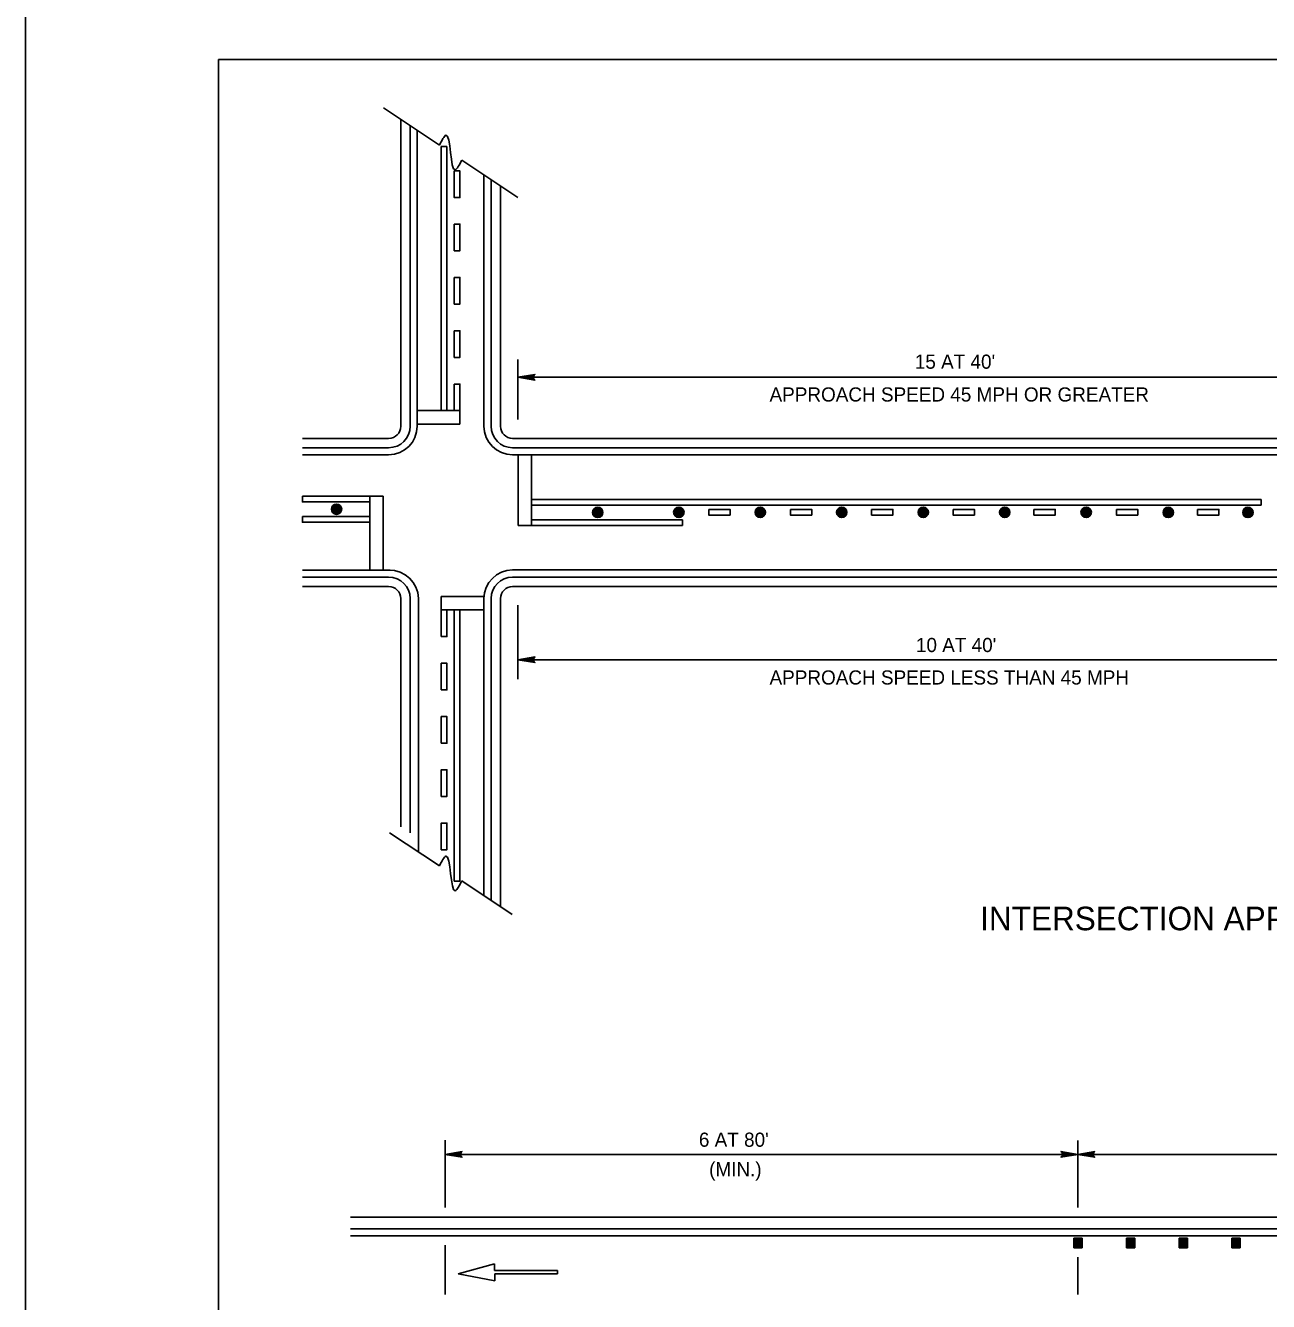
# Model space of a CAD drawing. Extents: x 639362 to 641108, y 298458 to 299646.
# Drawn here: x 639362.3 to 639626, y 298773.7 to 299044.4 of the extents above; entities that cross this region are included whole.
import ezdxf

# ---------------------------------------------------------------- set-up
doc = ezdxf.new("R2010")
doc.units = 0
for name, color, linetype in [('1', 7, 'Continuous'), ('2', 7, 'Continuous'), ('3', 7, 'Continuous'), ('PLT-BNDY', 7, 'Continuous')]:
    doc.layers.add(name, color=color, linetype=linetype)

# ---------------------------------------------------------------- blocks, each defined once
blk = doc.blocks.new('RARROW')
at = {"layer": '3'}
blk.add_lwpolyline([(-2.2695, 0.285), (-2.184875, 0.12075), (0, 0), (-2.2695, 0.285), (-2.38575, 0.384625), (0, 0), (-2.183125, -0.108), (-2.262875, -0.2705), (0, 0), (-2.38575, -0.379125), (-2.262875, -0.2705)], dxfattribs=at)

msp = doc.modelspace()

# ---------------------------------------------------------------- linework, layer by layer
at = {"layer": '1'}
for q in [(640189.27, 299037.19), (639403.27, 298473.19)]:
    msp.add_line((639403.27, 299037.19), q, dxfattribs=at)
at = {"layer": '2'}
for p, q in [((639450.1, 299019.03), (639438.22, 299026.95)), ((639441.9, 298959.38), (639441.9, 299024.5)), ((639443.9, 298959.38), (639443.9, 299023.16)), ((639445.4, 298959.38), (639445.4, 299022.16)), ((639450.51, 298962.69), (639450.51, 299018.73)), ((639450.51, 299018.73), (639451.71, 299018.73)), ((639451.71, 299018.73), (639451.71, 298962.69)), ((639466.76, 299007.92), (639454.86, 299015.86)), ((639459.55, 298959.38), (639459.55, 299012.73)), ((639461.05, 298959.38), (639461.05, 299011.73)), ((639463.05, 298959.38), (639463.05, 299010.4)), ((639466.77, 298973.53), (639466.77, 298960.81)), ((639466.77, 298969.77), (639638.59, 298969.77)), ((639445.4, 298962.69), (639454.45, 298962.69)), ((639451.71, 298962.69), (639450.51, 298962.69)), ((639454.45, 298962.7), (639454.45, 298959.83)), ((639445.4, 298959.83), (639454.45, 298959.83)), ((639421.03, 298956.81), (639439.33, 298956.81)), ((639421.03, 298954.81), (639439.33, 298954.81)), ((639465.63, 298956.81), (639777.38, 298956.81)), ((639465.63, 298954.81), (639777.38, 298954.81)), ((639421.03, 298953.31), (639439.33, 298953.31)), ((639465.63, 298953.31), (639777.38, 298953.31)), ((639466.78, 298953.31), (639466.78, 298938.35)), ((639469.64, 298953.31), (639469.64, 298938.35)), ((639438.18, 298944.52), (639435.33, 298944.52)), ((639435.33, 298928.83), (639435.33, 298944.52)), ((639438.18, 298928.83), (639438.18, 298944.52)), ((639624.41, 298943.86), (639469.63, 298943.86)), ((639469.63, 298943.86), (639469.63, 298942.66)), ((639624.41, 298942.66), (639624.41, 298943.86)), ((639469.63, 298942.66), (639624.41, 298942.66)), ((639466.78, 298938.35), (639469.64, 298938.35)), ((639501.67, 298939.55), (639469.64, 298939.55)), ((639469.64, 298939.55), (639469.64, 298938.35)), ((639469.64, 298938.35), (639501.67, 298938.35)), ((639501.67, 298938.35), (639501.67, 298939.55)), ((639421.03, 298928.83), (639439.69, 298928.83)), ((639421.03, 298927.38), (639439.33, 298927.38)), ((639465.63, 298928.88), (639777.38, 298928.88)), ((639465.63, 298927.38), (639777.38, 298927.38)), ((639421.03, 298925.38), (639439.33, 298925.38)), ((639465.63, 298925.38), (639777.38, 298925.38)), ((639441.9, 298922.81), (639441.9, 298874.4)), ((639443.9, 298922.81), (639443.9, 298873.07)), ((639445.69, 298922.83), (639445.69, 298869.02)), ((639450.51, 298923.24), (639450.51, 298920.39)), ((639459.57, 298923.24), (639450.51, 298923.24)), ((639459.55, 298922.81), (639459.55, 298859.78)), ((639461.05, 298922.81), (639461.05, 298858.78)), ((639463.05, 298922.81), (639463.05, 298857.44)), ((639459.55, 298920.39), (639450.51, 298920.39)), ((639454.45, 298920.39), (639453.25, 298920.39)), ((639453.25, 298920.39), (639453.25, 298862.84)), ((639453.25, 298862.84), (639453.25, 298920.39)), ((639453.25, 298920.39), (639454.45, 298920.39)), ((639454.45, 298862.84), (639454.45, 298920.39)), ((639454.45, 298920.39), (639454.45, 298862.84)), ((639466.77, 298921.38), (639466.77, 298905.73)), ((639466.77, 298909.84), (639638.59, 298909.84)), ((639439.54, 298873.12), (639450.1, 298866.08)), ((639454.45, 298862.84), (639453.25, 298862.84)), ((639454.86, 298862.91), (639465.53, 298855.8)), ((639451.32, 298807.88), (639451.32, 298793.58)), ((639585.52, 298807.8), (639585.52, 298793.58)), ((639451.32, 298804.88), (639585.52, 298804.88)), ((639585.52, 298804.88), (639797.99, 298804.88)), ((639431.25, 298791.58), (639952.64, 298791.58)), ((639431.25, 298789.08), (639952.64, 298789.08)), ((639431.25, 298787.58), (639952.64, 298787.58)), ((639584.64, 298787.09), (639586.41, 298787.09)), ((639584.64, 298785.05), (639584.64, 298787.09)), ((639584.81, 298786.92), (639586.23, 298786.92)), ((639584.81, 298785.23), (639584.81, 298786.92)), ((639584.99, 298786.74), (639586.06, 298786.74)), ((639584.99, 298785.41), (639584.99, 298786.74)), ((639585.17, 298785.59), (639585.17, 298786.56)), ((639585.17, 298786.56), (639585.88, 298786.56)), ((639585.88, 298786.56), (639585.88, 298785.59)), ((639586.06, 298786.74), (639586.06, 298785.41)), ((639586.23, 298786.92), (639586.23, 298785.23)), ((639586.41, 298787.09), (639586.41, 298785.05)), ((639595.82, 298787.09), (639597.59, 298787.09)), ((639595.82, 298785.05), (639595.82, 298787.09)), ((639596, 298786.92), (639597.42, 298786.92)), ((639596, 298785.23), (639596, 298786.92)), ((639596.17, 298786.74), (639597.24, 298786.74)), ((639596.17, 298785.41), (639596.17, 298786.74)), ((639596.35, 298785.59), (639596.35, 298786.56)), ((639596.35, 298786.56), (639597.06, 298786.56)), ((639597.06, 298786.56), (639597.06, 298785.59)), ((639597.24, 298786.74), (639597.24, 298785.41)), ((639597.42, 298786.92), (639597.42, 298785.23)), ((639597.59, 298787.09), (639597.59, 298785.05)), ((639607, 298787.09), (639608.78, 298787.09)), ((639607, 298785.05), (639607, 298787.09)), ((639607.18, 298786.92), (639608.6, 298786.92)), ((639607.18, 298785.23), (639607.18, 298786.92)), ((639607.36, 298786.74), (639608.42, 298786.74)), ((639607.36, 298785.41), (639607.36, 298786.74)), ((639607.54, 298785.59), (639607.54, 298786.56)), ((639607.54, 298786.56), (639608.24, 298786.56)), ((639608.24, 298786.56), (639608.24, 298785.59)), ((639608.42, 298786.74), (639608.42, 298785.41)), ((639608.6, 298786.92), (639608.6, 298785.23)), ((639608.78, 298787.09), (639608.78, 298785.05)), ((639618.19, 298787.09), (639619.96, 298787.09)), ((639618.19, 298785.05), (639618.19, 298787.09)), ((639618.36, 298786.92), (639619.78, 298786.92)), ((639618.36, 298785.23), (639618.36, 298786.92)), ((639618.54, 298786.74), (639619.61, 298786.74)), ((639618.54, 298785.41), (639618.54, 298786.74)), ((639618.72, 298785.59), (639618.72, 298786.56)), ((639618.72, 298786.56), (639619.43, 298786.56)), ((639619.43, 298786.56), (639619.43, 298785.59)), ((639619.61, 298786.74), (639619.61, 298785.41)), ((639619.78, 298786.92), (639619.78, 298785.23)), ((639619.96, 298787.09), (639619.96, 298785.05)), ((639451.32, 298785.58), (639451.32, 298775.16)), ((639586.41, 298785.05), (639584.64, 298785.05)), ((639586.23, 298785.23), (639584.81, 298785.23)), ((639586.06, 298785.41), (639584.99, 298785.41)), ((639585.88, 298785.59), (639585.17, 298785.59)), ((639585.35, 298786.39), (639585.7, 298786.39)), ((639585.35, 298785.76), (639585.35, 298786.39)), ((639585.7, 298785.76), (639585.35, 298785.76)), ((639585.52, 298786.21), (639585.52, 298785.94)), ((639585.7, 298786.39), (639585.7, 298785.76)), ((639597.59, 298785.05), (639595.82, 298785.05)), ((639597.42, 298785.23), (639596, 298785.23)), ((639597.24, 298785.41), (639596.17, 298785.41)), ((639597.06, 298785.59), (639596.35, 298785.59)), ((639596.53, 298786.39), (639596.88, 298786.39)), ((639596.53, 298785.76), (639596.53, 298786.39)), ((639596.88, 298785.76), (639596.53, 298785.76)), ((639596.7, 298786.21), (639596.7, 298785.94)), ((639596.88, 298786.39), (639596.88, 298785.76)), ((639608.78, 298785.05), (639607, 298785.05)), ((639608.6, 298785.23), (639607.18, 298785.23)), ((639608.42, 298785.41), (639607.36, 298785.41)), ((639608.24, 298785.59), (639607.54, 298785.59)), ((639607.71, 298786.39), (639608.07, 298786.39)), ((639607.71, 298785.76), (639607.71, 298786.39)), ((639608.07, 298785.76), (639607.71, 298785.76)), ((639607.89, 298786.21), (639607.89, 298785.94)), ((639608.07, 298786.39), (639608.07, 298785.76)), ((639619.96, 298785.05), (639618.19, 298785.05)), ((639619.78, 298785.23), (639618.36, 298785.23)), ((639619.61, 298785.41), (639618.54, 298785.41)), ((639619.43, 298785.59), (639618.72, 298785.59)), ((639618.9, 298786.39), (639619.25, 298786.39)), ((639618.9, 298785.76), (639618.9, 298786.39)), ((639619.25, 298785.76), (639618.9, 298785.76)), ((639619.07, 298786.21), (639619.07, 298785.94)), ((639619.25, 298786.39), (639619.25, 298785.76)), ((639461.79, 298781.66), (639454.07, 298779.55)), ((639461.79, 298780.22), (639461.79, 298781.66)), ((639585.52, 298783.05), (639585.52, 298775.16)), ((639454.07, 298779.55), (639461.87, 298778.07)), ((639475.12, 298780.22), (639461.79, 298780.22)), ((639461.87, 298778.07), (639461.87, 298779.51)), ((639461.87, 298779.51), (639475.12, 298779.51)), ((639475.12, 298779.51), (639475.12, 298780.22))]:
    msp.add_line(p, q, dxfattribs=at)
for points in [[(639453.25, 299013.56), (639454.45, 299013.56), (639454.45, 299007.91), (639453.25, 299007.91)], [(639453.25, 299002.26), (639454.45, 299002.26), (639454.45, 298996.6), (639453.25, 298996.6)], [(639453.25, 298990.95), (639454.45, 298990.95), (639454.45, 298985.3), (639453.25, 298985.3)], [(639453.25, 298979.65), (639454.45, 298979.65), (639454.45, 298973.99), (639453.25, 298973.99)], [(639453.25, 298968.34), (639454.45, 298968.34), (639454.45, 298962.69), (639453.25, 298962.69)], [(639421.03, 298944.52), (639435.33, 298944.52), (639435.33, 298943.32), (639421.03, 298943.32)], [(639507.23, 298941.72), (639511.75, 298941.72), (639511.75, 298940.52), (639507.23, 298940.52)], [(639524.56, 298941.72), (639529.08, 298941.72), (639529.08, 298940.52), (639524.56, 298940.52)], [(639541.79, 298941.72), (639546.31, 298941.72), (639546.31, 298940.52), (639541.79, 298940.52)], [(639559.06, 298941.72), (639563.58, 298941.72), (639563.58, 298940.52), (639559.06, 298940.52)], [(639576.2, 298941.72), (639580.72, 298941.72), (639580.72, 298940.52), (639576.2, 298940.52)], [(639593.72, 298941.72), (639598.24, 298941.72), (639598.24, 298940.52), (639593.72, 298940.52)], [(639610.93, 298941.72), (639615.45, 298941.72), (639615.45, 298940.52), (639610.93, 298940.52)], [(639421.03, 298940.21), (639435.33, 298940.21), (639435.33, 298939.01), (639421.03, 298939.01)], [(639450.51, 298914.73), (639451.71, 298914.73), (639451.71, 298920.39), (639450.51, 298920.39)], [(639450.51, 298903.43), (639451.71, 298903.43), (639451.71, 298909.08), (639450.51, 298909.08)], [(639450.51, 298892.12), (639451.71, 298892.12), (639451.71, 298897.78), (639450.51, 298897.78)], [(639450.51, 298880.82), (639451.71, 298880.82), (639451.71, 298886.47), (639450.51, 298886.47)], [(639450.51, 298869.51), (639451.71, 298869.51), (639451.71, 298875.17), (639450.51, 298875.17)]]:
    msp.add_lwpolyline(points, close=True, dxfattribs=at)
for centre, radius in [((639428.28, 298941.77), 1.1), ((639428.28, 298941.77), 1.02), ((639428.28, 298941.77), 0.946), ((639428.28, 298941.77), 0.868), ((639428.28, 298941.77), 0.789), ((639428.28, 298941.77), 0.711), ((639428.28, 298941.77), 0.633), ((639428.28, 298941.77), 0.554), ((639428.28, 298941.77), 0.476), ((639428.28, 298941.77), 0.398), ((639428.28, 298941.77), 0.32), ((639428.28, 298941.77), 0.241), ((639428.28, 298941.77), 0.163), ((639428.28, 298941.77), 0.0846), ((639483.68, 298941.1), 1.1), ((639483.68, 298941.1), 1.02), ((639483.68, 298941.1), 0.946), ((639483.68, 298941.1), 0.868), ((639483.68, 298941.1), 0.789), ((639483.68, 298941.1), 0.711), ((639483.68, 298941.1), 0.633), ((639483.68, 298941.1), 0.554), ((639483.68, 298941.1), 0.476), ((639483.68, 298941.1), 0.398), ((639483.68, 298941.1), 0.32), ((639483.68, 298941.1), 0.241), ((639483.68, 298941.1), 0.163), ((639483.68, 298941.1), 0.0846), ((639500.89, 298941.11), 1.1), ((639500.89, 298941.11), 1.02), ((639500.89, 298941.11), 0.946), ((639500.89, 298941.11), 0.868), ((639500.89, 298941.11), 0.789), ((639500.89, 298941.11), 0.711), ((639500.89, 298941.11), 0.633), ((639500.89, 298941.11), 0.554), ((639500.89, 298941.11), 0.476), ((639500.89, 298941.11), 0.398), ((639500.89, 298941.11), 0.32), ((639500.89, 298941.11), 0.241), ((639500.89, 298941.11), 0.163), ((639500.89, 298941.11), 0.0846), ((639518.17, 298941.11), 1.1), ((639518.17, 298941.11), 1.02), ((639518.17, 298941.11), 0.946), ((639518.17, 298941.11), 0.868), ((639518.17, 298941.11), 0.789), ((639518.17, 298941.11), 0.711), ((639518.17, 298941.11), 0.633), ((639518.17, 298941.11), 0.554), ((639518.17, 298941.11), 0.476), ((639518.17, 298941.11), 0.398), ((639518.17, 298941.11), 0.32), ((639518.17, 298941.11), 0.241), ((639518.17, 298941.11), 0.163), ((639518.17, 298941.11), 0.0846), ((639535.45, 298941.11), 1.1), ((639535.45, 298941.11), 1.02), ((639535.45, 298941.11), 0.946), ((639535.45, 298941.11), 0.868), ((639535.45, 298941.11), 0.789), ((639535.45, 298941.11), 0.711), ((639535.45, 298941.11), 0.633), ((639535.45, 298941.11), 0.554), ((639535.45, 298941.11), 0.476), ((639535.45, 298941.11), 0.398), ((639535.45, 298941.11), 0.32), ((639535.45, 298941.11), 0.241), ((639535.45, 298941.11), 0.163), ((639535.45, 298941.11), 0.0846), ((639552.73, 298941.11), 1.1), ((639552.73, 298941.11), 1.02), ((639552.73, 298941.11), 0.946), ((639552.73, 298941.11), 0.868), ((639552.73, 298941.11), 0.789), ((639552.73, 298941.11), 0.711), ((639552.73, 298941.11), 0.633), ((639552.73, 298941.11), 0.554), ((639552.73, 298941.11), 0.476), ((639552.73, 298941.11), 0.398), ((639552.73, 298941.11), 0.32), ((639552.73, 298941.11), 0.241), ((639552.73, 298941.11), 0.163), ((639552.73, 298941.11), 0.0846), ((639570.01, 298941.11), 1.1), ((639570.01, 298941.11), 1.02), ((639570.01, 298941.11), 0.946), ((639570.01, 298941.11), 0.868), ((639570.01, 298941.11), 0.789), ((639570.01, 298941.11), 0.711), ((639570.01, 298941.11), 0.633), ((639570.01, 298941.11), 0.554), ((639570.01, 298941.11), 0.476), ((639570.01, 298941.11), 0.398), ((639570.01, 298941.11), 0.32), ((639570.01, 298941.11), 0.241), ((639570.01, 298941.11), 0.163), ((639570.01, 298941.11), 0.0846), ((639587.29, 298941.11), 1.1), ((639587.29, 298941.11), 1.02), ((639587.29, 298941.11), 0.946), ((639587.29, 298941.11), 0.868), ((639587.29, 298941.11), 0.789), ((639587.29, 298941.11), 0.711), ((639587.29, 298941.11), 0.633), ((639587.29, 298941.11), 0.554), ((639587.29, 298941.11), 0.476), ((639587.29, 298941.11), 0.398), ((639587.29, 298941.11), 0.32), ((639587.29, 298941.11), 0.241), ((639587.29, 298941.11), 0.163), ((639587.29, 298941.11), 0.0846), ((639604.71, 298941.1), 1.1), ((639604.71, 298941.1), 1.02), ((639604.71, 298941.1), 0.946), ((639604.71, 298941.1), 0.868), ((639604.71, 298941.1), 0.789), ((639604.71, 298941.1), 0.711), ((639604.71, 298941.1), 0.633), ((639604.71, 298941.1), 0.554), ((639604.71, 298941.1), 0.476), ((639604.71, 298941.1), 0.398), ((639604.71, 298941.1), 0.32), ((639604.71, 298941.1), 0.241), ((639604.71, 298941.1), 0.163), ((639604.71, 298941.1), 0.0846), ((639621.61, 298941.1), 1.1), ((639621.61, 298941.1), 1.02), ((639621.61, 298941.1), 0.946), ((639621.61, 298941.1), 0.868), ((639621.61, 298941.1), 0.789), ((639621.61, 298941.1), 0.711), ((639621.61, 298941.1), 0.633), ((639621.61, 298941.1), 0.554), ((639621.61, 298941.1), 0.476), ((639621.61, 298941.1), 0.398), ((639621.61, 298941.1), 0.32), ((639621.61, 298941.1), 0.241), ((639621.61, 298941.1), 0.163), ((639621.61, 298941.1), 0.0846)]:
    msp.add_circle(centre, radius, dxfattribs=at)
for centre, radius, start, end in [((639439.33, 298959.38), 4.57, 270, 0), ((639439.33, 298959.38), 6.07, 270, 0), ((639439.33, 298959.38), 2.57, 270, 0), ((639465.63, 298959.38), 6.07, 180, 270), ((639465.63, 298959.38), 4.57, 180, 270), ((639465.63, 298959.38), 2.57, 180, 270), ((639439.51, 298922.65), 6.18, 1.6739, 91.6739), ((639439.33, 298922.81), 4.57, 0, 90), ((639465.63, 298922.81), 6.07, 90, 180), ((639465.63, 298922.81), 4.57, 90, 180), ((639439.33, 298922.81), 2.57, 0, 90), ((639465.63, 298922.81), 2.57, 90, 180)]:
    msp.add_arc(centre, radius, start, end, dxfattribs=at)
for points in [[(639454.86, 299015.86), (639453.46, 299013.77), (639451.49, 299021.12), (639450.1, 299019.03)], [(639450.1, 298866.08), (639451.49, 298868.17), (639453.47, 298860.82), (639454.86, 298862.91)]]:
    msp.add_spline(points, degree=3, dxfattribs=at)
at = {"layer": 'PLT-BNDY'}
msp.add_lwpolyline([(639362.31, 299051.63), (640203.31, 299051.63), (640203.31, 298457.63), (639362.31, 298457.63)], close=True, dxfattribs=at)

# ---------------------------------------------------------------- block references
at = {"layer": '2', "xscale": 1.5089217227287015, "yscale": 1.5711553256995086, "rotation": 180}
for p in [(639466.77, 298969.77), (639466.77, 298909.84), (639451.32, 298804.88), (639585.52, 298804.88)]:
    msp.add_blockref('RARROW', p, dxfattribs=at)
at = {"layer": '2', "xscale": 1.5089217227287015, "yscale": 1.5711553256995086}
msp.add_blockref('RARROW', (639585.52, 298804.88), dxfattribs=at)

# ---------------------------------------------------------------- texts
at = {"layer": '2'}
for s, height, p in [("15 AT 40'", 3, (639550.94, 298971.58)), ('APPROACH SPEED 45 MPH OR GREATER', 3, (639520.13, 298964.62)), ("10 AT 40'", 3, (639551.18, 298911.46)), ('APPROACH SPEED LESS THAN 45 MPH', 3, (639520.13, 298904.57)), ('INTERSECTION APPROACH', 5, (639564.81, 298852.43)), ("6 AT 80'", 3, (639505.14, 298806.49)), ('(MIN.)', 3, (639507.31, 298800.22))]:
    msp.add_text(s, height=height, dxfattribs=at).set_placement(p)

doc.saveas('drawing.dxf')
